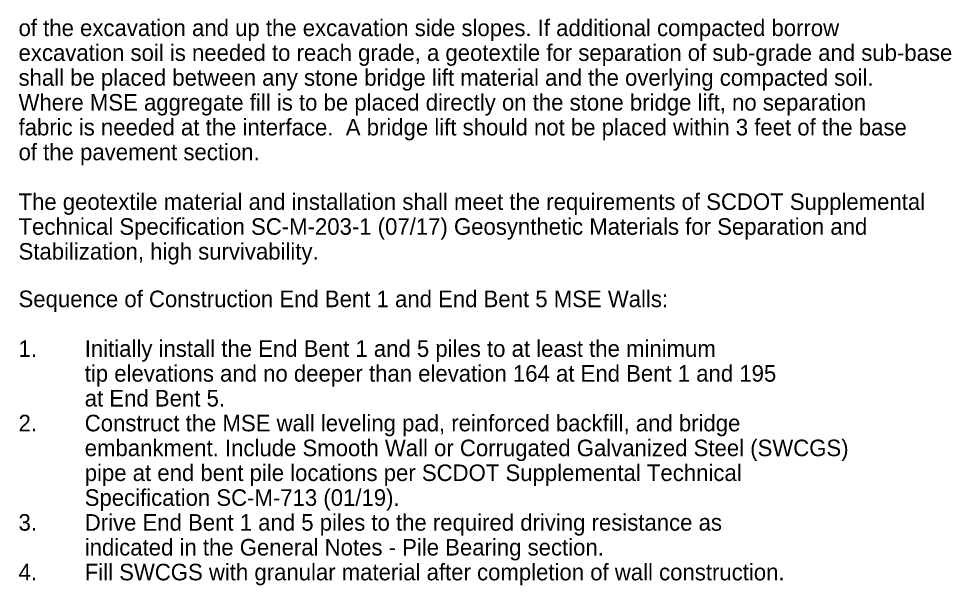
# Model space of a CAD drawing. Extents: x 96 to 240, y 601 to 689.
# Drawn here: x 184.29 to 212.47, y 627.81 to 644.92 of the extents above; entities that cross this region are included whole.
import ezdxf

# ---------------------------------------------------------------- set-up
doc = ezdxf.new("R2010")
doc.units = 0
doc.layers.add('BR_TEXT', color=7, linetype='Continuous')

msp = doc.modelspace()

# ---------------------------------------------------------------- texts
at = {"layer": 'BR_TEXT'}
for s, p in [('of the excavation and up the excavation side slopes. If additional compacted borrow ', (184.285, 644.394)), ('excavation soil is needed to reach grade, a geotextile for separation of sub-grade and sub-base ', (184.285, 643.644)), ('shall be placed between any stone bridge lift material and the overlying compacted soil.  ', (184.285, 642.894)), ('Where MSE aggregate fill is to be placed directly on the stone bridge lift, no separation ', (184.285, 642.144)), ('fabric is needed at the interface.  A bridge lift should not be placed within 3 feet of the base ', (184.285, 641.394)), ('of the pavement section.  ', (184.285, 640.644)), ('The geotextile material and installation shall meet the requirements of SCDOT Supplemental ', (184.285, 639.144)), ('Technical Specification SC-M-203-1 (07/17) Geosynthetic Materials for Separation and ', (184.285, 638.394)), ('Stabilization, high survivability.  ', (184.285, 637.644)), ('Sequence of Construction End Bent 1 and End Bent 5 MSE Walls:', (184.285, 636.208)), ('1.', (184.285, 634.708)), ('Initially install the End Bent 1 and 5 piles to at least the minimum', (186.285, 634.708)), ('tip elevations and no deeper than elevation 164 at End Bent 1 and 195', (186.285, 633.958)), ('at End Bent 5.', (186.285, 633.208)), ('2.', (184.285, 632.458)), ('Construct the MSE wall leveling pad, reinforced backfill, and bridge', (186.285, 632.458)), ('embankment. Include Smooth Wall or Corrugated Galvanized Steel (SWCGS)', (186.285, 631.708)), ('pipe at end bent pile locations per SCDOT Supplemental Technical', (186.285, 630.958)), ('Specification SC-M-713 (01/19).', (186.285, 630.208)), ('3.', (184.285, 629.458)), ('Drive End Bent 1 and 5 piles to the required driving resistance as', (186.285, 629.458)), ('indicated in the General Notes - Pile Bearing section.', (186.285, 628.708)), ('4.', (184.285, 627.958)), ('Fill SWCGS with granular material after completion of wall construction.', (186.285, 627.958))]:
    msp.add_text(s, height=0.5, dxfattribs=at).set_placement(p)

doc.saveas('drawing.dxf')
